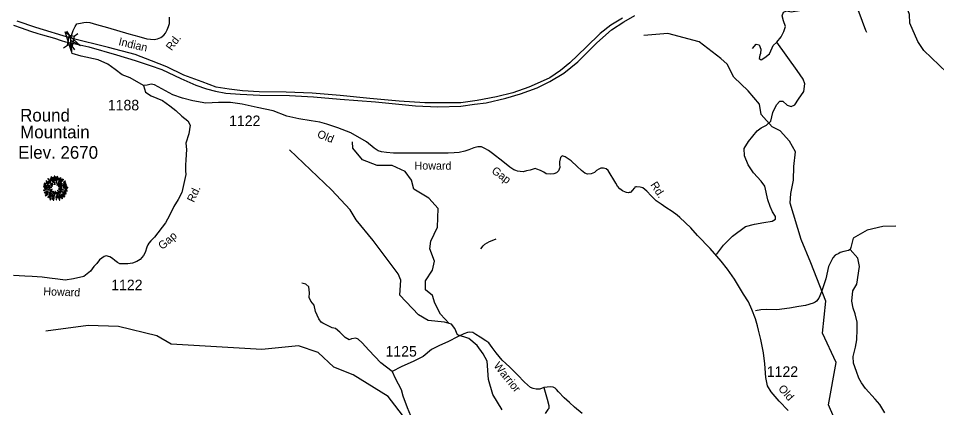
# Model space of a CAD drawing. Extents: x 990631 to 1056237, y 535999 to 585651.
# Drawn here: x 1021960 to 1032860, y 557410 to 562025 of the extents above; entities that cross this region are included whole.
import ezdxf

# ---------------------------------------------------------------- set-up
doc = ezdxf.new("R2010")
doc.units = 0
for name, color, linetype in [('Exist Geographical Mountain Summit CELL', 7, 'Continuous'), ('Exist Geographical Mountain Summit Elevation Number Label', 7, 'Continuous'), ('Exist Geographical Mountain Summit Label', 7, 'Continuous'), ('Exist Hydrographic Creek Single Shore', 7, 'Continuous'), ('Exist Road Non-System Type 51', 7, 'Continuous'), ('Exist Road Primary Interstate Divided Center Attributed', 7, 'Continuous'), ('Exist Road Secondary Structure Standard Bridge Attributed CELL', 7, 'Continuous'), ('Exist Road Secondary Structure Standard Bridge CELL', 7, 'Continuous'), ('Exist Road Secondary Type 41 Attributed', 7, 'Continuous'), ('Exist Road Secondary Type 51 Attributed', 7, 'Continuous'), ('Exist Road Secondary Type 51 Label', 7, 'Continuous'), ('Exist Road Secondary Type 51 Number Label', 7, 'Continuous')]:
    doc.layers.add(name, color=color, linetype=linetype)

msp = doc.modelspace()

# ---------------------------------------------------------------- linework, layer by layer
at = {"layer": 'Exist Geographical Mountain Summit CELL'}
for points in [[(1022262, 560047), (1022303, 560038), (1022304, 560041), (1022263, 560052)], [(1022265, 560066), (1022287, 560058), (1022288, 560061), (1022266, 560072)], [(1022287, 560077), (1022312, 560061), (1022315, 560064), (1022289, 560081)], [(1022288, 560096), (1022327, 560066), (1022329, 560068), (1022291, 560101)], [(1022303, 560049), (1022334, 560037), (1022335, 560040), (1022305, 560053)], [(1022308, 560121), (1022344, 560084), (1022347, 560086), (1022312, 560126)], [(1022316, 560093), (1022349, 560064), (1022351, 560066), (1022319, 560098)], [(1022336, 560122), (1022351, 560101), (1022353, 560102), (1022340, 560126)], [(1022340, 560055), (1022365, 560036), (1022367, 560039), (1022342, 560058)], [(1022346, 560144), (1022373, 560077), (1022376, 560078), (1022352, 560147)], [(1022359, 560068), (1022373, 560052), (1022375, 560054), (1022362, 560071)], [(1022380, 560092), (1022383, 560093), (1022374, 560141), (1022369, 560140)], [(1022385, 560154), (1022389, 560102), (1022392, 560102), (1022391, 560155)], [(1022390, 560080), (1022392, 560051), (1022394, 560052), (1022394, 560081)], [(1022401, 560100), (1022405, 560100), (1022409, 560147), (1022403, 560147)], [(1022413, 560071), (1022428, 560148), (1022422, 560150), (1022410, 560072)], [(1022416, 560049), (1022419, 560048), (1022468, 560132), (1022462, 560136)], [(1022431, 560106), (1022434, 560105), (1022444, 560132), (1022439, 560134)], [(1022434, 560031), (1022436, 560028), (1022485, 560064), (1022481, 560069)], [(1022437, 560051), (1022440, 560049), (1022495, 560113), (1022491, 560118)], [(1022451, 560028), (1022452, 560026), (1022530, 560054), (1022529, 560059)], [(1022475, 560122), (1022454, 560089), (1022457, 560088), (1022479, 560119)], [(1022495, 560056), (1022523, 560071), (1022520, 560076), (1022494, 560058)], [(1022495, 560079), (1022497, 560076), (1022520, 560093), (1022516, 560096)], [(1022258, 559988), (1022259, 559983), (1022295, 559994), (1022293, 559997)], [(1022259, 560026), (1022331, 560019), (1022332, 560022), (1022259, 560031)], [(1022268, 559961), (1022270, 559956), (1022316, 559976), (1022314, 559981)], [(1022271, 560009), (1022301, 560010), (1022301, 560014), (1022270, 560014)], [(1022279, 559924), (1022282, 559920), (1022310, 559941), (1022308, 559944)], [(1022285, 559945), (1022314, 559961), (1022312, 559965), (1022283, 559950)], [(1022304, 560000), (1022305, 559995), (1022338, 560003), (1022337, 560007)], [(1022310, 559904), (1022313, 559902), (1022353, 559949), (1022351, 559952)], [(1022321, 559954), (1022324, 559951), (1022359, 559979), (1022357, 559981)], [(1022325, 559936), (1022344, 559954), (1022341, 559956), (1022321, 559939)], [(1022331, 559985), (1022333, 559981), (1022362, 559996), (1022361, 559999)], [(1022340, 560025), (1022357, 560023), (1022357, 560025), (1022341, 560029)], [(1022353, 559914), (1022357, 559912), (1022384, 559971), (1022381, 559972)], [(1022360, 559964), (1022363, 559961), (1022373, 559977), (1022372, 559978)], [(1022374, 559869), (1022379, 559868), (1022392, 559957), (1022389, 559958)], [(1022400, 559973), (1022404, 559936), (1022408, 559936), (1022403, 559973)], [(1022416, 559964), (1022425, 559934), (1022429, 559936), (1022418, 559965)], [(1022424, 559984), (1022463, 559949), (1022465, 559953), (1022426, 559987)], [(1022430, 559962), (1022481, 559887), (1022485, 559890), (1022433, 559963)], [(1022436, 560001), (1022496, 559989), (1022497, 559994), (1022437, 560005)], [(1022449, 559982), (1022528, 559944), (1022529, 559949), (1022451, 559985)], [(1022450, 560015), (1022450, 560012), (1022480, 560012), (1022481, 560017)], [(1022489, 559948), (1022514, 559935), (1022516, 559938), (1022491, 559952)], [(1022493, 560014), (1022546, 560017), (1022546, 560022), (1022494, 560017)], [(1022497, 560028), (1022534, 560034), (1022532, 560040), (1022496, 560030)], [(1022503, 559972), (1022524, 559964), (1022526, 559968), (1022504, 559975)], [(1022508, 560002), (1022535, 560000), (1022535, 560004), (1022509, 560005)], [(1022512, 559985), (1022541, 559978), (1022541, 559983), (1022513, 559989)], [(1022350, 559936), (1022325, 559896), (1022328, 559894), (1022354, 559933)], [(1022335, 559877), (1022340, 559874), (1022351, 559899), (1022347, 559901)], [(1022365, 559879), (1022377, 559922), (1022373, 559922), (1022360, 559880)], [(1022406, 559914), (1022410, 559872), (1022414, 559873), (1022410, 559914)], [(1022426, 559897), (1022420, 559927), (1022417, 559927), (1022421, 559896)], [(1022430, 559919), (1022448, 559869), (1022452, 559871), (1022433, 559920)], [(1022441, 559925), (1022457, 559895), (1022461, 559897), (1022445, 559926)], [(1022463, 559936), (1022493, 559907), (1022496, 559909), (1022465, 559938)], [(1022480, 559937), (1022510, 559911), (1022513, 559915), (1022481, 559939)]]:
    msp.add_lwpolyline(points, close=True, dxfattribs=at)
at = {"layer": 'Exist Hydrographic Creek Single Shore'}
for points in [[(1032636, 561750), (1032543, 561969), (1032538, 562070), (1032438, 562342), (1031993, 562764), (1031954, 562847), (1031944, 563041), (1031851, 563545), (1031737, 563865), (1031680, 563932), (1031643, 564074), (1031643, 564317), (1031563, 564686)], [(1031123, 559834), (1031131, 559950), (1031160, 560105), (1031164, 560268), (1031185, 560444), (1031114, 560569), (1031001, 560691), (1030909, 560737), (1030776, 560885), (1030759, 561006), (1030621, 561165), (1030454, 561328), (1030374, 561483), (1030299, 561550), (1030040, 561746), (1029668, 561846), (1029383, 561821)], [(1034637, 560252), (1034608, 560359), (1034582, 560427), (1034526, 560441), (1034440, 560435), (1034320, 560466), (1034258, 560504), (1033904, 560600), (1033744, 560632), (1033638, 560697), (1033644, 560722), (1033571, 560852), (1033326, 560916), (1033205, 561063), (1033071, 561298), (1032707, 561644), (1032636, 561750)], [(1027074, 558408), (1027022, 558463), (1026971, 558518), (1026905, 558647), (1026875, 558739), (1026791, 558805), (1026791, 558912), (1026875, 559040), (1026901, 559147), (1026846, 559291), (1026857, 559382), (1026934, 559548), (1026942, 559772), (1026831, 559895), (1026655, 559998), (1026625, 560108), (1026552, 560211), (1026397, 560281), (1026221, 560281), (1026044, 560347), (1025930, 560487), (1025926, 560561)], [(1027704, 557385), (1027594, 557566), (1027541, 557744), (1027523, 557961), (1027476, 558047), (1027407, 558147), (1027307, 558228), (1027172, 558275), (1027141, 558347), (1027100, 558399), (1027018, 558425), (1026826, 558443), (1026711, 558510), (1026489, 558743), (1026500, 558923), (1026470, 558997), (1026171, 559390), (1025969, 559637), (1025898, 559753), (1025678, 559994), (1025180, 560466)], [(1032840, 554362), (1032839, 554844), (1032797, 555370), (1032719, 555798), (1032562, 556103), (1032117, 556795), (1031763, 557189), (1031640, 557295), (1031575, 557443), (1031668, 557945), (1031507, 558291), (1031544, 558671), (1031367, 559127), (1031251, 559405), (1031123, 559834)], [(1026558, 557268), (1026350, 557541), (1025934, 557799), (1025703, 557889), (1025517, 558064), (1025286, 558144), (1024851, 558100), (1023774, 558163), (1023602, 558263), (1023147, 558372), (1022787, 558385), (1022286, 558318)]]:
    msp.add_lwpolyline(points, dxfattribs=at)
at = {"layer": 'Exist Road Non-System Type 51'}
for points in [[(1030962, 561744), (1031013, 561806), (1031046, 561869), (1031067, 561928), (1031042, 561994), (1031025, 562053), (1031042, 562099), (1031080, 562116), (1031134, 562103), (1031234, 562120), (1031297, 562183), (1031380, 562333), (1031460, 562388), (1031523, 562396), (1031610, 562400), (1031702, 562429), (1031748, 562417), (1031836, 562325), (1031936, 562099), (1032016, 561886), (1032028, 561861)], [(1030248, 559224), (1030331, 559337), (1030436, 559441), (1030590, 559558), (1030699, 559584), (1030808, 559604), (1030908, 559621), (1030946, 559646), (1030946, 559676), (1030912, 559730), (1030883, 559793), (1030858, 559872), (1030820, 560035), (1030779, 560094), (1030687, 560194), (1030624, 560290), (1030578, 560395), (1030574, 560483), (1030628, 560566), (1030728, 560692), (1030779, 560729), (1030841, 560758), (1030891, 560808), (1030916, 560908), (1030958, 561000), (1031000, 561042), (1031034, 561042), (1031084, 560996), (1031134, 560979), (1031176, 561000), (1031222, 561067), (1031284, 561159), (1031297, 561247), (1031276, 561304), (1031205, 561405), (1030962, 561744)], [(1030674, 561668), (1030716, 561718), (1030753, 561710), (1030774, 561660), (1030770, 561610), (1030762, 561589), (1030753, 561551), (1030779, 561534), (1030820, 561560), (1030875, 561606), (1030908, 561677), (1030921, 561702), (1030962, 561744)], [(1032375, 559561), (1032221, 559556), (1032037, 559515), (1031870, 559418), (1031840, 559310), (1031834, 559283), (1031813, 559272), (1031757, 559262), (1031715, 559249), (1031698, 559237), (1031655, 559219), (1031627, 559184), (1031577, 559082), (1031544, 558936), (1031495, 558782), (1031463, 558709), (1031434, 558674), (1031419, 558660), (1031393, 558649), (1031302, 558622), (1031226, 558609), (1031113, 558590), (1030962, 558569), (1030841, 558574), (1030772, 558571), (1030710, 558557)], [(1027451, 559294), (1027476, 559327), (1027497, 559348), (1027552, 559381), (1027602, 559399), (1027633, 559410)], [(1032246, 557349), (1032184, 557446), (1032130, 557510), (1032015, 557635), (1031967, 557703), (1031937, 557758), (1031908, 557839), (1031874, 557938), (1031868, 558015), (1031898, 558128), (1031913, 558214), (1031917, 558342), (1031918, 558424), (1031894, 558521), (1031870, 558590), (1031853, 558674), (1031865, 558795), (1031911, 558875), (1031945, 559084), (1031924, 559180), (1031834, 559283)], [(1026396, 557839), (1026261, 557942), (1026119, 558092), (1026040, 558180), (1025994, 558222), (1025965, 558234), (1025915, 558226), (1025885, 558213), (1025839, 558243), (1025777, 558305), (1025726, 558347), (1025685, 558356), (1025576, 558410), (1025555, 558422), (1025526, 558464), (1025488, 558548), (1025471, 558623), (1025430, 558673), (1025413, 558715), (1025417, 558770), (1025409, 558841), (1025371, 558874), (1025325, 558887)]]:
    msp.add_lwpolyline(points, dxfattribs=at)
at = {"layer": 'Exist Road Primary Interstate Divided Center Attributed'}
for points in [[(1022582, 561733), (1022795, 561686), (1023126, 561592), (1023345, 561525), (1023525, 561468), (1023661, 561419), (1023887, 561310), (1024068, 561234), (1024192, 561189), (1024301, 561163), (1024421, 561137), (1024591, 561125), (1024828, 561114), (1025178, 561110), (1025464, 561095), (1025781, 561065), (1026199, 561035), (1026673, 560986), (1026940, 560978), (1027212, 560984), (1027374, 561007), (1027514, 561025), (1027746, 561080), (1027919, 561129), (1028119, 561201), (1028269, 561276), (1028435, 561374), (1028601, 561509), (1028827, 561735), (1029000, 561890), (1029147, 561984), (1029279, 562059)], [(1029132, 562029), (1028992, 561946), (1028868, 561844), (1028699, 561682), (1028507, 561497), (1028394, 561407), (1028269, 561320), (1028153, 561268), (1028021, 561211), (1027829, 561143), (1027637, 561094), (1027407, 561053), (1027212, 561025), (1027095, 561023), (1026786, 561023), (1026481, 561042), (1026131, 561076), (1025781, 561109), (1025449, 561140), (1025137, 561151), (1024817, 561155), (1024621, 561166), (1024463, 561185), (1024308, 561210), (1024143, 561271), (1023924, 561350), (1023721, 561451), (1023540, 561523), (1023348, 561595), (1023028, 561681), (1022584, 561791)], [(1021902, 561944), (1021995, 561914), (1022105, 561875), (1022190, 561845), (1022248, 561828), (1022316, 561810), (1022389, 561791), (1022469, 561764), (1022521, 561748), (1022582, 561733)], [(1022584, 561791), (1022168, 561916), (1021947, 561992)]]:
    msp.add_lwpolyline(points, dxfattribs=at)
at = {"layer": 'Exist Road Secondary Structure Standard Bridge Attributed CELL'}
msp.add_lwpolyline([(1022592, 561632), (1022517, 561864), (1022698, 561700), (1022583, 561762)], close=True, dxfattribs=at)
at = {"layer": 'Exist Road Secondary Structure Standard Bridge CELL'}
for p, q in [((1022566, 561826), (1022536, 561872)), ((1022621, 561815), (1022666, 561846)), ((1022497, 561676), (1022543, 561707)), ((1022629, 561651), (1022598, 561696))]:
    msp.add_line(p, q, dxfattribs=at)
msp.add_lwpolyline([(1022543, 561707), (1022566, 561826), (1022622, 561815), (1022598, 561696)], close=True, dxfattribs=at)
at = {"layer": 'Exist Road Secondary Type 41 Attributed'}
msp.add_lwpolyline([(1028199, 557647), (1028238, 557510), (1028255, 557434), (1028256, 557400), (1028245, 557388), (1028212, 557339)], dxfattribs=at)
at = {"layer": 'Exist Road Secondary Type 51 Attributed'}
for points in [[(1022584, 561791), (1022595, 561834), (1022612, 561881), (1022636, 561928), (1022655, 561959), (1022719, 561973), (1022737, 561977), (1022769, 561980), (1022809, 561977), (1022887, 561954), (1023018, 561918), (1023273, 561843), (1023388, 561809), (1023485, 561784), (1023529, 561778), (1023573, 561775), (1023611, 561782), (1023650, 561800), (1023687, 561825), (1023706, 561851), (1023727, 561890), (1023744, 561929), (1023753, 561963), (1023754, 561993), (1023752, 562038)], [(1022582, 561733), (1022583, 561759), (1022584, 561791)], [(1023445, 561229), (1023289, 561319), (1023191, 561355), (1023110, 561420), (1023020, 561483), (1022907, 561533), (1022707, 561578), (1022599, 561609), (1022587, 561655), (1022582, 561733)], [(1028385, 560324), (1028385, 560288), (1028388, 560265), (1028386, 560257), (1028370, 560216), (1028349, 560194), (1028316, 560180), (1028271, 560176), (1028226, 560180), (1028196, 560200), (1028156, 560223), (1028116, 560239), (1028093, 560245), (1028035, 560227), (1027992, 560216), (1027954, 560205), (1027918, 560209), (1027886, 560214), (1027864, 560223), (1027843, 560230), (1027794, 560261), (1027711, 560326), (1027587, 560423), (1027542, 560457), (1027499, 560484), (1027459, 560500), (1027414, 560500), (1027367, 560491), (1027308, 560468), (1027261, 560451), (1027191, 560434), (1027135, 560430), (1027063, 560428), (1026879, 560425), (1026730, 560428), (1026631, 560428), (1026553, 560425), (1026413, 560425), (1026330, 560434), (1026269, 560441), (1026229, 560455), (1026182, 560488), (1026094, 560560), (1025907, 560668), (1025752, 560727), (1025622, 560772), (1025538, 560794), (1025437, 560812), (1025289, 560833), (1025147, 560864), (1024985, 560927), (1024794, 560970), (1024616, 561006), (1024477, 561026), (1024335, 561026), (1024185, 561019), (1024032, 561049), (1023910, 561078), (1023795, 561118), (1023577, 561235), (1023537, 561245), (1023490, 561231), (1023445, 561229)], [(1023445, 561229), (1023469, 561150), (1023537, 561107), (1023672, 561051), (1023759, 560986), (1023829, 560934), (1023901, 560866), (1023971, 560810), (1023998, 560758), (1023984, 560657)], [(1023984, 560657), (1023948, 560547), (1023957, 560470), (1023948, 560348), (1023944, 560284), (1023942, 560240), (1023944, 560218), (1023948, 560173), (1023901, 559960), (1023856, 559876), (1023804, 559793), (1023753, 559687), (1023708, 559602), (1023575, 559431), (1023531, 559387), (1023507, 559360), (1023496, 559342), (1023485, 559312), (1023465, 559251), (1023445, 559215), (1023404, 559165), (1023368, 559143), (1023314, 559123), (1023260, 559114), (1023208, 559114), (1023166, 559116), (1023137, 559132), (1023107, 559154), (1023078, 559177), (1023047, 559199), (1023004, 559210), (1022977, 559201), (1022950, 559183), (1022925, 559161), (1022891, 559118), (1022855, 559082), (1022817, 559028), (1022736, 558963), (1022615, 558938), (1022516, 558920), (1022428, 558934), (1022331, 558945), (1022244, 558956), (1022122, 558963), (1022037, 558967), (1021904, 558976)], [(1031099, 557376), (1030989, 557488), (1030897, 557596), (1030853, 557670), (1030834, 557766), (1030819, 557931), (1030803, 558060), (1030772, 558217), (1030744, 558327), (1030735, 558380), (1030711, 558463), (1030668, 558573), (1030625, 558666), (1030567, 558756), (1030459, 558934), (1030378, 559053), (1030304, 559145), (1030171, 559296), (1030023, 559449), (1029942, 559543), (1029813, 559663), (1029782, 559690), (1029719, 559735), (1029647, 559784), (1029589, 559822), (1029530, 559863), (1029472, 559919), (1029420, 559975), (1029373, 560016), (1029339, 560025), (1029299, 560027), (1029292, 560027), (1029288, 560027), (1029282, 560023), (1029278, 560022), (1029272, 560016), (1029247, 559983), (1029230, 559965), (1029224, 559961), (1029212, 559960), (1029198, 559958), (1029178, 559959), (1029166, 559963), (1029131, 559982), (1029115, 559993), (1029100, 560004), (1029073, 560036), (1029052, 560073), (1028963, 560221), (1028936, 560243), (1028905, 560250), (1028876, 560250), (1028849, 560236), (1028824, 560223), (1028797, 560196), (1028761, 560180), (1028716, 560178), (1028685, 560189), (1028646, 560223), (1028595, 560268), (1028523, 560335), (1028451, 560385), (1028417, 560396), (1028394, 560374), (1028385, 560324)], [(1028199, 557647), (1028148, 557630), (1028108, 557628), (1028072, 557637), (1028040, 557649), (1027968, 557710), (1027883, 557797), (1027795, 557888), (1027747, 557935), (1027703, 557974), (1027632, 558061), (1027586, 558123), (1027543, 558177), (1027507, 558201), (1027442, 558246), (1027390, 558277), (1027354, 558299), (1027317, 558304), (1027290, 558302), (1027247, 558283), (1027172, 558250), (1027067, 558194), (1026951, 558144), (1026863, 558099), (1026764, 558016), (1026653, 557961), (1026504, 557894), (1026396, 557839), (1026434, 557760), (1026470, 557691), (1026503, 557625), (1026525, 557548), (1026576, 557413), (1026636, 557270)], [(1028652, 557341), (1028563, 557416), (1028504, 557469), (1028437, 557527), (1028371, 557597), (1028347, 557623), (1028330, 557641), (1028310, 557654), (1028278, 557656), (1028199, 557647)]]:
    msp.add_lwpolyline(points, dxfattribs=at)

# ---------------------------------------------------------------- texts
at = {"layer": 'Exist Geographical Mountain Summit Elevation Number Label'}
msp.add_text('Elev. 2670', height=150, dxfattribs=at).set_placement((1021958, 560361))
at = {"layer": 'Exist Geographical Mountain Summit Label'}
for s, p in [('Round', (1021981, 560802)), ('Mountain', (1021981, 560603))]:
    msp.add_text(s, height=150, dxfattribs=at).set_placement(p)
at = {"layer": 'Exist Road Secondary Type 51 Label'}
for s, rotation, p in [('Indian', 346.6806, (1023143, 561709)), ('Rd.', 53.3496, (1023779, 561634)), ('Old', 337.9727, (1025499, 560619)), ('Howard', 359.66, (1026663, 560233)), ('Gap', 323.6663, (1027569, 560200)), ('Rd.', 302.8857, (1029458, 560052)), ('Rd.', 65.2586, (1024043, 559836)), ('Gap', 40.9828, (1023670, 559277)), ('Howard', 358.1422, (1022255, 558742)), ('Warrior', 309.1641, (1027595, 557904)), ('Old', 311.1437, (1030974, 557631))]:
    msp.add_text(s, height=95, rotation=rotation, dxfattribs=at).set_placement(p)
at = {"layer": 'Exist Road Secondary Type 51 Number Label'}
for s, p in [('1188', (1023022, 560934)), ('1122', (1024461, 560748)), ('1122', (1023062, 558802)), ('1125', (1026318, 558015)), ('1122', (1030844, 557775))]:
    msp.add_text(s, height=125, dxfattribs=at).set_placement(p)

doc.saveas('drawing.dxf')
